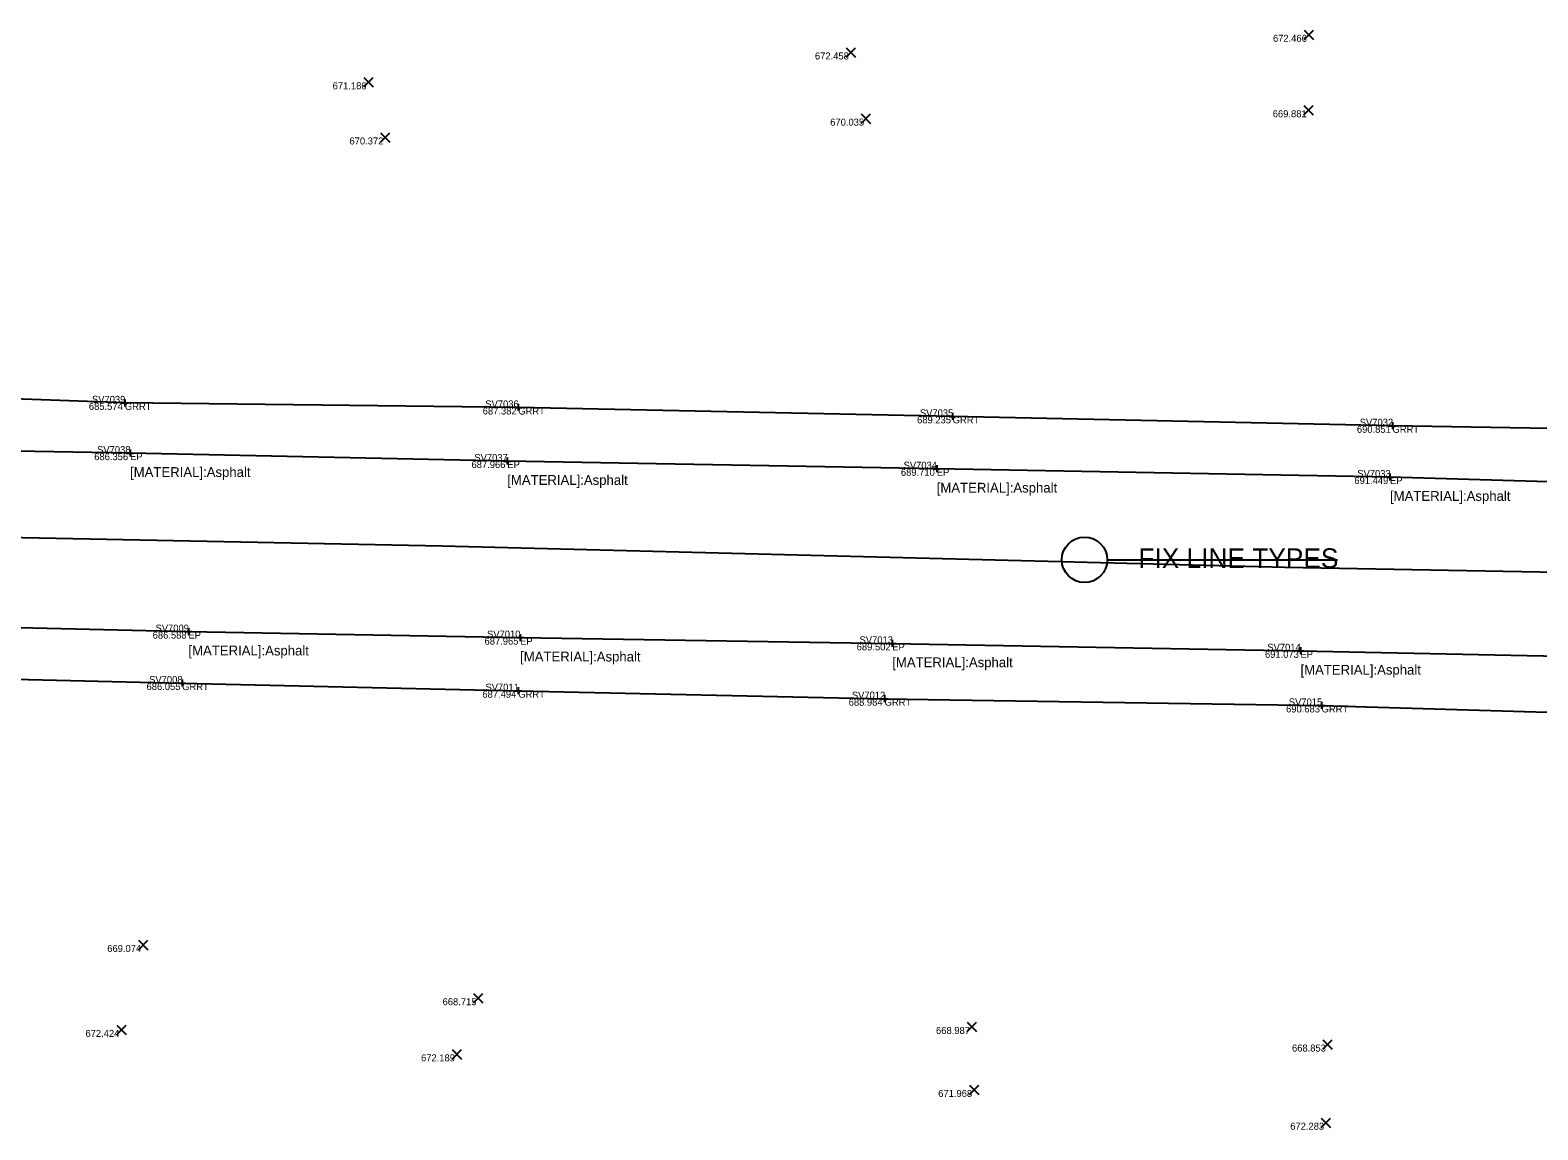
# Model space of a CAD drawing. Extents: x 1659932 to 1663108, y 619867 to 620611.
# Drawn here: x 1660787.2 to 1661002.1, y 620159.1 to 620315.9 of the extents above; entities that cross this region are included whole.
import ezdxf

# ---------------------------------------------------------------- set-up
doc = ezdxf.new("R2010")
doc.units = 0
for name, color, linetype in [('PM_X_CL_Dashed', 7, 'Continuous'), ('PV_X_EOP', 7, 'Continuous'), ('RD_X_GR_Rt', 7, 'Continuous'), ('SC_Scratch6', 7, 'Continuous'), ('SV_X_Random_Point', 7, 'Continuous'), ('SV_X_Shot_Marker', 7, 'Continuous'), ('SV_X_Text', 7, 'Continuous'), ('SV_X_Text_Comment', 7, 'Continuous'), ('SV_X_Text_Elevation', 7, 'Continuous'), ('SV_X_Text_Name', 7, 'Continuous')]:
    doc.layers.add(name, color=color, linetype=linetype)

msp = doc.modelspace()

# ---------------------------------------------------------------- linework, layer by layer
at = {"layer": 'PM_X_CL_Dashed'}
msp.add_lwpolyline([(1660473.33, 620249.8), (1660569.82, 620247.52), (1660683.17, 620245.58), (1660845.9, 620242.37), (1660966.03, 620239.29), (1661085.35, 620237.14), (1661180.4, 620235.01), (1661204.65, 620234.52)], dxfattribs=at)
at = {"layer": 'PV_X_EOP'}
for points in [[(1661208.92, 620246.9), (1661156.94, 620248.21), (1661087.29, 620250.6), (1661037.39, 620250.48), (1660981.01, 620252.16), (1660916.41, 620253.34), (1660855.2, 620254.44), (1660801.44, 620255.57), (1660749.64, 620256.49), (1660700.03, 620257.78), (1660643.44, 620258.64), (1660593.17, 620259.57)], [(1660597.37, 620234.1), (1660651.64, 620233.44), (1660703.42, 620232.61), (1660757.32, 620231.35), (1660809.76, 620230.12), (1660857.03, 620229.26), (1660910.07, 620228.44), (1660968.25, 620227.38), (1661028.27, 620226.15), (1661081.58, 620225.11), (1661140.41, 620223.53), (1661201.71, 620222.7)]]:
    msp.add_lwpolyline(points, dxfattribs=at)
at = {"layer": 'RD_X_GR_Rt'}
for points in [[(1661224.69, 620250.79), (1661156.18, 620253.35), (1661087.54, 620257.19), (1661037.26, 620258.5), (1660981.37, 620259.47), (1660918.68, 620260.81), (1660856.77, 620262.08), (1660800.7, 620262.74), (1660750.31, 620264.54), (1660700.27, 620265.16), (1660644.43, 620266.52), (1660592.86, 620267.53)], [(1660596.86, 620226.32), (1660650.68, 620225.81), (1660702.7, 620224.83), (1660759.05, 620223.97), (1660808.86, 620222.78), (1660856.77, 620221.69), (1660908.98, 620220.55), (1660971.26, 620219.59), (1661027.54, 620217.92), (1661083.51, 620217.29), (1661139.61, 620218.11), (1661215.13, 620218.24)]]:
    msp.add_lwpolyline(points, dxfattribs=at)
at = {"layer": 'SC_Scratch6'}
msp.add_line((1660940.72, 620240.36), (1660973.52, 620240.36), dxfattribs=at)
msp.add_circle((1660937.48, 620240.36), 3.24, dxfattribs=at)
at = {"layer": 'SV_X_Random_Point'}
for p, q in [((1660968.77, 620314.56), (1660970.1, 620315.89)), ((1660968.77, 620315.89), (1660970.1, 620314.56)), ((1660903.48, 620312.04), (1660904.82, 620313.38)), ((1660903.48, 620313.38), (1660904.82, 620312.04)), ((1660834.75, 620307.79), (1660836.08, 620309.13)), ((1660834.75, 620309.13), (1660836.08, 620307.79)), ((1660968.71, 620303.8), (1660970.05, 620305.14)), ((1660968.71, 620305.14), (1660970.05, 620303.8)), ((1660905.64, 620302.6), (1660906.97, 620303.94)), ((1660905.64, 620303.94), (1660906.97, 620302.6)), ((1660837.11, 620299.92), (1660838.45, 620301.26)), ((1660837.11, 620301.26), (1660838.45, 620299.92)), ((1660802.64, 620184.76), (1660803.98, 620186.1)), ((1660802.64, 620186.1), (1660803.98, 620184.76)), ((1660850.38, 620177.18), (1660851.72, 620178.51)), ((1660850.38, 620178.51), (1660851.72, 620177.18)), ((1660799.54, 620172.66), (1660800.87, 620173.99)), ((1660799.54, 620173.99), (1660800.87, 620172.66)), ((1660920.74, 620173.07), (1660922.07, 620174.41)), ((1660920.74, 620174.41), (1660922.07, 620173.07)), ((1660971.44, 620170.56), (1660972.77, 620171.9)), ((1660971.44, 620171.9), (1660972.77, 620170.56)), ((1660847.33, 620169.16), (1660848.66, 620170.5)), ((1660847.33, 620170.5), (1660848.66, 620169.16)), ((1660921.06, 620164.09), (1660922.39, 620165.42)), ((1660921.06, 620165.42), (1660922.39, 620164.09)), ((1660971.19, 620159.41), (1660972.52, 620160.74)), ((1660971.19, 620160.74), (1660972.52, 620159.41))]:
    msp.add_line(p, q, dxfattribs=at)
at = {"layer": 'SV_X_Shot_Marker'}
for p, q in [((1660800.7, 620263.24), (1660800.7, 620262.24)), ((1660800.2, 620262.74), (1660801.2, 620262.74)), ((1660800.7, 620262.74), (1660800.7, 620262.74)), ((1660856.27, 620262.08), (1660857.27, 620262.08)), ((1660856.77, 620262.58), (1660856.77, 620261.58)), ((1660856.77, 620262.08), (1660856.77, 620262.08)), ((1660918.68, 620261.31), (1660918.68, 620260.31)), ((1660918.18, 620260.81), (1660919.18, 620260.81)), ((1660918.68, 620260.81), (1660918.68, 620260.81)), ((1660980.87, 620259.47), (1660981.87, 620259.47)), ((1660981.37, 620259.97), (1660981.37, 620258.97)), ((1660981.37, 620259.47), (1660981.37, 620259.47)), ((1660800.94, 620255.57), (1660801.94, 620255.57)), ((1660801.44, 620256.07), (1660801.44, 620255.07)), ((1660801.44, 620255.57), (1660801.44, 620255.57)), ((1660855.2, 620254.94), (1660855.2, 620253.94)), ((1660854.7, 620254.44), (1660855.7, 620254.44)), ((1660855.2, 620254.44), (1660855.2, 620254.44)), ((1660915.91, 620253.34), (1660916.91, 620253.34)), ((1660916.41, 620253.84), (1660916.41, 620252.84)), ((1660916.41, 620253.34), (1660916.41, 620253.34)), ((1660981.01, 620252.66), (1660981.01, 620251.66)), ((1660980.51, 620252.16), (1660981.51, 620252.16)), ((1660981.01, 620252.16), (1660981.01, 620252.16)), ((1660809.26, 620230.12), (1660810.26, 620230.12)), ((1660809.76, 620230.62), (1660809.76, 620229.62)), ((1660809.76, 620230.12), (1660809.76, 620230.12)), ((1660856.53, 620229.26), (1660857.53, 620229.26)), ((1660857.03, 620229.76), (1660857.03, 620228.76)), ((1660857.03, 620229.26), (1660857.03, 620229.26)), ((1660910.07, 620228.94), (1660910.07, 620227.94)), ((1660909.57, 620228.44), (1660910.57, 620228.44)), ((1660910.07, 620228.44), (1660910.07, 620228.44)), ((1660967.75, 620227.38), (1660968.75, 620227.38)), ((1660968.25, 620227.88), (1660968.25, 620226.88)), ((1660968.25, 620227.38), (1660968.25, 620227.38)), ((1660808.36, 620222.78), (1660809.36, 620222.78)), ((1660808.86, 620223.28), (1660808.86, 620222.28)), ((1660808.86, 620222.78), (1660808.86, 620222.78)), ((1660856.27, 620221.69), (1660857.27, 620221.69)), ((1660856.77, 620222.19), (1660856.77, 620221.19)), ((1660856.77, 620221.69), (1660856.77, 620221.69)), ((1660908.48, 620220.55), (1660909.48, 620220.55)), ((1660908.98, 620221.05), (1660908.98, 620220.05)), ((1660908.98, 620220.55), (1660908.98, 620220.55)), ((1660970.76, 620219.59), (1660971.76, 620219.59)), ((1660971.26, 620220.09), (1660971.26, 620219.09)), ((1660971.26, 620219.59), (1660971.26, 620219.59))]:
    msp.add_line(p, q, dxfattribs=at)

# ---------------------------------------------------------------- texts
at = {"layer": 'SC_Scratch6'}
msp.add_text('FIX LINE TYPES', height=2.8, dxfattribs=at).set_placement((1660945.15, 620239.19))
at = {"layer": 'SV_X_Text'}
for p in [(1660801.44, 620252.17), (1660855.2, 620251.04), (1660916.41, 620249.94), (1660981.01, 620248.76), (1660809.76, 620226.72), (1660857.03, 620225.86), (1660910.07, 620225.04), (1660968.25, 620223.98)]:
    msp.add_text('[MATERIAL]:Asphalt', height=1.4, dxfattribs=at).set_placement(p)
at = {"layer": 'SV_X_Text_Comment'}
for s, p in [('GRRT', (1660800.7, 620261.74)), ('GRRT', (1660856.77, 620261.08)), ('GRRT', (1660918.68, 620259.81)), ('GRRT', (1660981.37, 620258.47)), ('EP', (1660801.44, 620254.57)), ('EP', (1660855.2, 620253.44)), ('EP', (1660916.41, 620252.34)), ('EP', (1660981.01, 620251.16)), ('EP', (1660809.76, 620229.12)), ('EP', (1660857.03, 620228.26)), ('EP', (1660910.07, 620227.44)), ('EP', (1660968.25, 620226.38)), ('GRRT', (1660808.86, 620221.78)), ('GRRT', (1660856.77, 620220.69)), ('GRRT', (1660908.98, 620219.55)), ('GRRT', (1660971.26, 620218.59))]:
    msp.add_text(s, height=1, dxfattribs=at).set_placement(p)
at = {"layer": 'SV_X_Text_Elevation'}
for s, p in [('672.466', (1660964.33, 620314.23)), ('672.458', (1660899.05, 620311.71)), ('671.186', (1660830.31, 620307.46)), ('669.881', (1660964.3, 620303.47)), ('670.035', (1660901.23, 620302.27)), ('670.372', (1660832.71, 620299.59)), ('685.574', (1660795.57, 620261.74)), ('687.382', (1660851.7, 620261.08)), ('689.235', (1660913.61, 620259.81)), ('690.851', (1660976.29, 620258.47)), ('686.356', (1660796.33, 620254.57)), ('687.966', (1660850.1, 620253.44)), ('689.710', (1660911.3, 620252.34)), ('691.449', (1660975.93, 620251.16)), ('686.588', (1660804.66, 620229.12)), ('687.965', (1660851.96, 620228.26)), ('689.502', (1660905, 620227.44)), ('691.073', (1660963.19, 620226.38)), ('686.055', (1660803.79, 620221.78)), ('687.494', (1660851.65, 620220.69)), ('688.984', (1660903.86, 620219.55)), ('690.683', (1660966.2, 620218.59)), ('669.074', (1660798.19, 620184.43)), ('668.715', (1660845.98, 620176.84)), ('672.424', (1660795.08, 620172.32)), ('668.987', (1660916.31, 620172.74)), ('668.853', (1660967.04, 620170.23)), ('672.189', (1660842.91, 620168.83)), ('671.968', (1660916.62, 620163.76)), ('672.283', (1660966.79, 620159.08))]:
    msp.add_text(s, height=1, dxfattribs=at).set_placement(p)
at = {"layer": 'SV_X_Text_Name'}
for s, p in [('SV7039', (1660796.01, 620262.74)), ('SV7036', (1660852.07, 620262.08)), ('SV7035', (1660914.01, 620260.81)), ('SV7032', (1660976.7, 620259.47)), ('SV7038', (1660796.74, 620255.57)), ('SV7037', (1660850.51, 620254.44)), ('SV7034', (1660911.69, 620253.34)), ('SV7033', (1660976.35, 620252.16)), ('SV7009', (1660805.07, 620230.12)), ('SV7010', (1660852.32, 620229.26)), ('SV7013', (1660905.41, 620228.44)), ('SV7014', (1660963.53, 620227.38)), ('SV7008', (1660804.16, 620222.78)), ('SV7011', (1660852.09, 620221.69)), ('SV7012', (1660904.31, 620220.55)), ('SV7015', (1660966.59, 620219.59))]:
    msp.add_text(s, height=1, dxfattribs=at).set_placement(p)

doc.saveas('drawing.dxf')
